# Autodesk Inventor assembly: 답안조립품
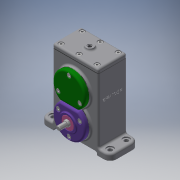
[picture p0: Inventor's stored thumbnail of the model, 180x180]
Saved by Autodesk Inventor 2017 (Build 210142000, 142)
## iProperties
Part Number: 답안조립품
Material: 일반
Document SubType Name: Assembly
Designer: 222
Mass: 1460.95 g
Surface Area: 1575.48 cm^2
Volume: 385.032 cm^3
Density: 3.79437 g/cm^3
Author: 222
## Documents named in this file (24)
- C:\Users\222\Desktop\600506V1040\답안조립품.iam
- C:\Users\222\Desktop\600506V1040\본체.ipt
- C:\Users\222\Desktop\600506V1040\Ű 4 x 4 x 12.ipt
- C:\Users\222\Desktop\600506V1040\Ű 5 x 5 x 12.ipt
- C:\Users\222\Desktop\600506V1040\개스킷 A.ipt
- C:\Users\222\Desktop\600506V1040\개스킷 B.ipt
- C:\Users\222\Desktop\600506V1040\개스킷 C.ipt
- C:\Users\222\Desktop\600506V1040\베어링 6001.ipt
- 베어링 6001.ipt
- C:\Users\222\Desktop\600506V1040\베어링 6002.ipt
- 베어링 6002.ipt
- C:\Users\222\Desktop\600506V1040\볼트 M4.ipt
- C:\Users\222\Desktop\600506V1040\스퍼기어 A.ipt
- C:\Users\222\Desktop\600506V1040\스퍼기어 B.ipt
- C:\Users\222\Desktop\600506V1040\오일 실 10 20 7.ipt
- C:\Users\222\Desktop\600506V1040\오일 실 12 22 7.ipt
- C:\Users\222\Desktop\600506V1040\축 A.ipt
- C:\Users\222\Desktop\600506V1040\축 B.ipt
- C:\Users\222\Desktop\600506V1040\칼라.ipt
- C:\Users\222\Desktop\600506V1040\커버 A.ipt
- C:\Users\222\Desktop\600506V1040\커버 B.ipt
- C:\Users\222\Desktop\600506V1040\커버 C.ipt
- C:\Users\222\Desktop\600506V1040\커버 D.ipt
- C:\Users\222\Desktop\600506V1040\커버 E.ipt
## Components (7 placed, 5 different names)
1. Ű 4 x 4 x 12:1
2. Ű 5 x 5 x 12:1
3. 개스킷 A:1
4. 개스킷 B:1
5. 개스킷 C:1
6. 개스킷 B:2
7. 개스킷 B:3
